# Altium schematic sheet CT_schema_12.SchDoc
size 145 x 119 mm
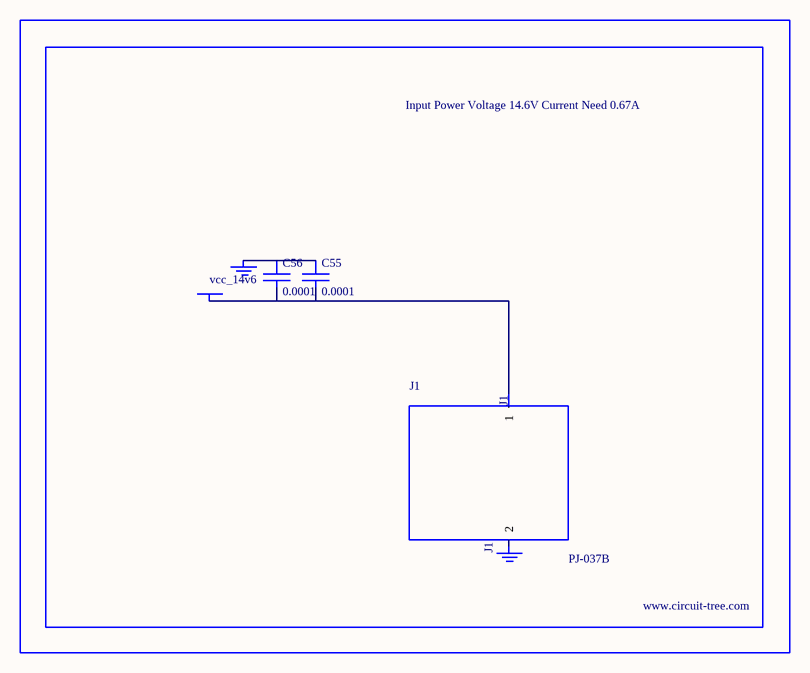
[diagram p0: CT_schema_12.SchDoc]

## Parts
BORDER11  (no value)
C55  0.0001  [EXV-9H]
C56  0.0001  [EXV-9H]
GND_INSTANCE_11_0  (no value)
GND_INSTANCE_11_1  (no value)
J1  PJ-037B  [PJ-037B_PACKAGE]
POWER_INSTANCE_11_0  vcc_14v6

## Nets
NetC55_1: C55.1 C56.1 GND_INSTANCE_11_0.0(GND)
NetC55_2: C55.2 C56.2 J1.1 POWER_INSTANCE_11_0.0(PWR)

Not connected (* = marked no-connect by the designer): GND_INSTANCE_11_1 0(GND); J1 2

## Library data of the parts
BORDER11 = BORDER_PAGE11
C55 C56 = EDK107M035A9HAA
GND_INSTANCE_11_0 GND_INSTANCE_11_1 = GND
POWER_INSTANCE_11_0 = PWR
